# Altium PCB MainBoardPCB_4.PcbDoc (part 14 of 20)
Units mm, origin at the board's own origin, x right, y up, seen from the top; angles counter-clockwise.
Board outline 333.63 x 349.38 mm, 16 copper layers (L1, L2 (GND), L3 (Sign), L4 (GND), L5 (Sign), L6 (PWR/GND), L7(PWR/GND), L8 (Plane_GND), L9 (PWR/GND), L10 (PWR/GND), L11 (PWR/GND), L12 (Sign), L13 (GND), L14 (Sign), L15 (GND), L16), stack 2.502 mm thick; 2205 components, 1648 nets, 8314 pads, 3172 vias.
Unrouted connection lines stored in the file: 5141.
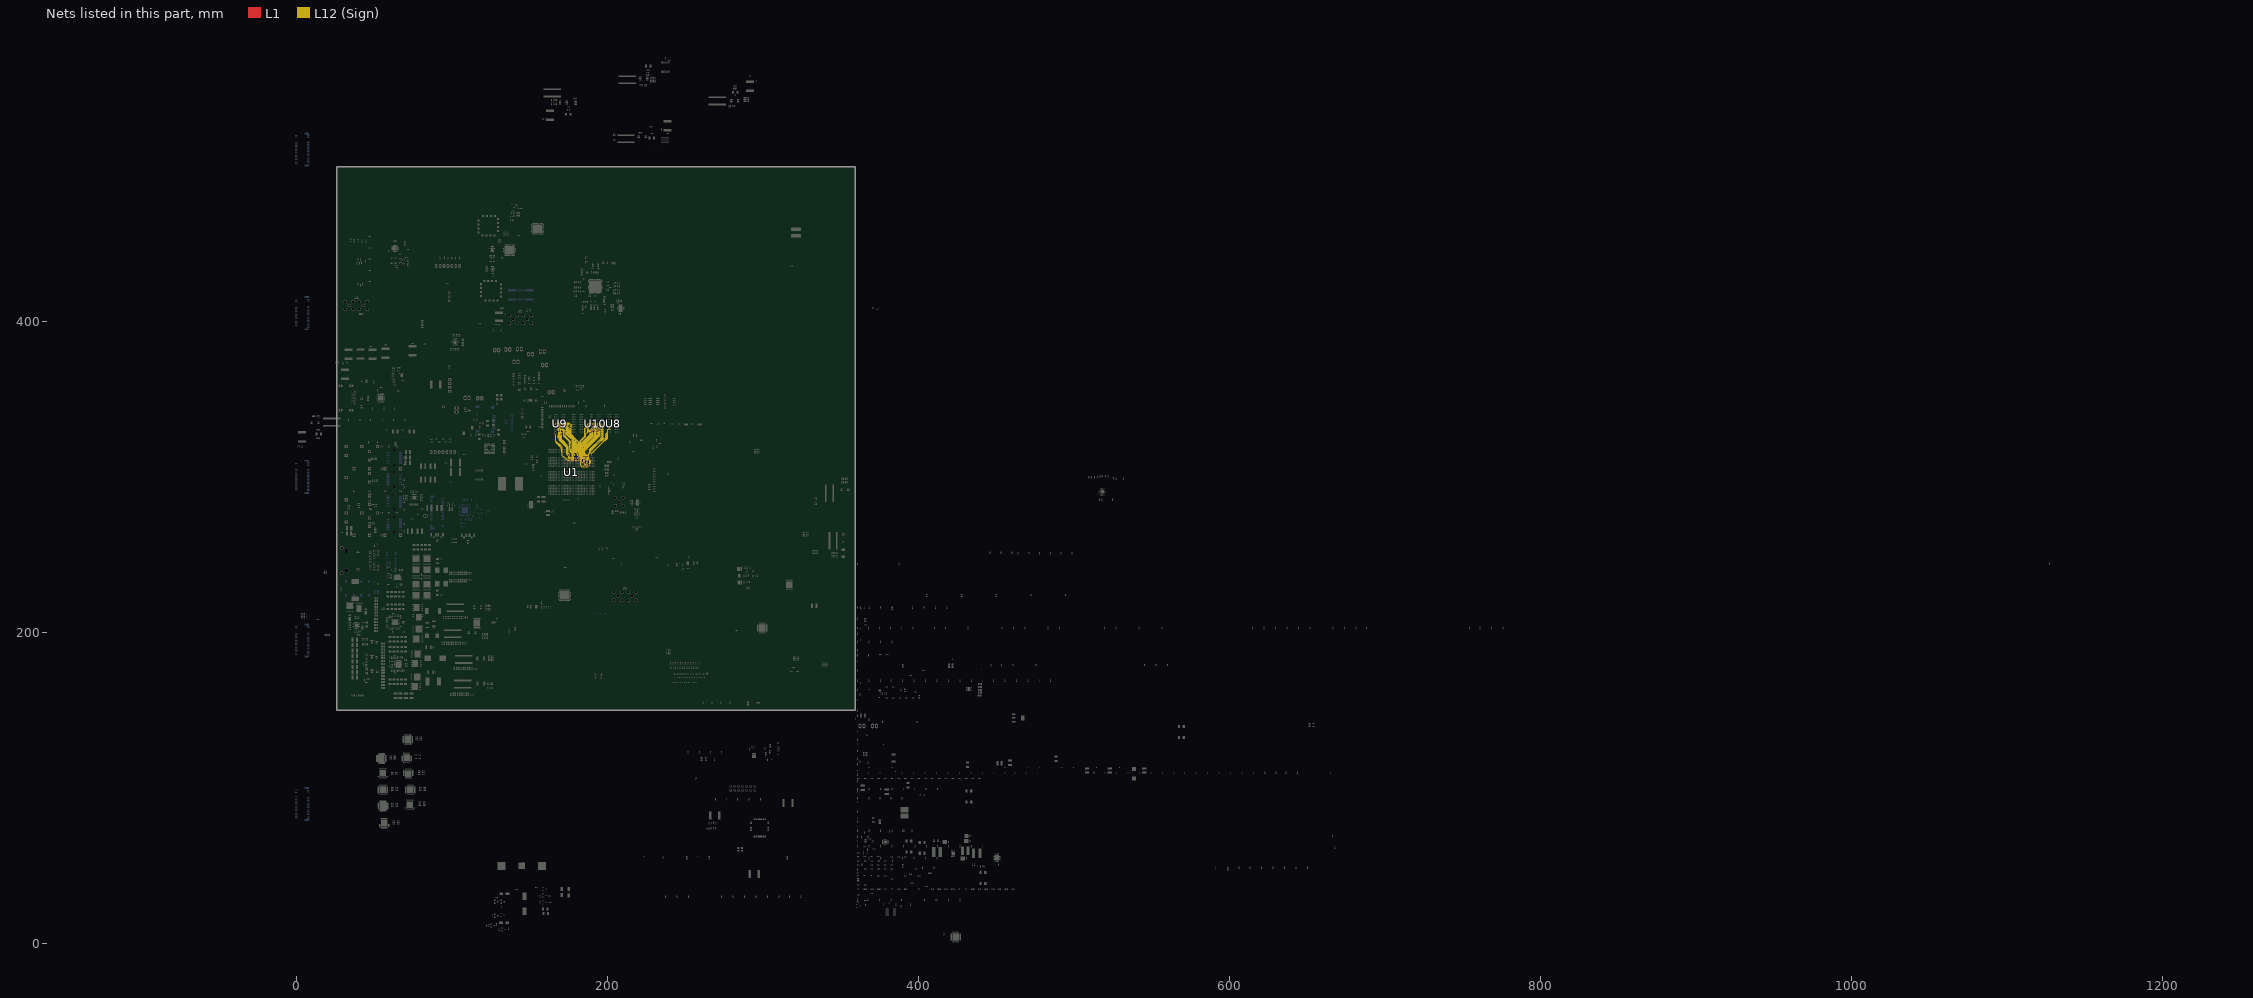
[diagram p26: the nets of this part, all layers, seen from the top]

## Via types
v1: diameter 0.5, hole 0.2, L1 to L16, tented both sides, 1153 vias
v2: diameter 0.5/0.35/0.35/0.35/0.35/0.35/0.35/0.35/0.35/0.35/0.35/0.35/0.35/0.35/0.35/0.5 (per signal layer), hole 0.2, L1 to L16, tented both sides, 548 vias
v3: diameter 0.5, hole 0.2, L1 to L16, 522 vias
v4: diameter 0.5/0.35/0.35/0.35/0.35/0.35/0.35/0.35/0.35/0.35/0.35/0.35/0.35/0.35/0.35/0.5 (per signal layer), hole 0.15, L1 to L16, tented both sides, 266 vias
v5: diameter 0.8, hole 0.4, L1 to L16, tented both sides, 164 vias
v6: diameter 0.35/0/0.35 (per signal layer), hole 0.127, L1 to L3 (Sign), tented both sides, 132 vias
v7: diameter 2.54, hole 1.02, L1 to L16, 125 vias
v8: diameter 1.4, hole 0.5, L1 to L16, tented both sides, 80 vias
v9: diameter 0.35, hole 0.127, L1 to L2 (GND), tented both sides, 36 vias
v10: diameter 0.4, hole 0.2, L1 to L16, 16 vias
v11: diameter 0.25, hole 0.2, L1 to L16, 16 vias
v12: diameter 5, hole 3, L1 to L16, 15 vias
v13: diameter 0.3, hole 0.2, L1 to L16, 15 vias
v14: diameter 0.45, hole 0.15, L1 to L16, 12 vias
v15: diameter 0.5/0.35/0.35/0.35/0.35/0.35/0.35/0.35/0.35/0.35/0.35/0.35/0.35/0.35/0.35/0.45 (per signal layer), hole 0.15, L1 to L16, tented both sides, 10 vias
v16: diameter 0.2/0/0.2 (per signal layer), hole 0.1, L1 to L3 (Sign), tented both sides, 9 vias
v17: diameter 0.4, hole 0.1, L1 to L16, 7 vias
v18: diameter 0.5, hole 0.2, L3 (Sign) to L6 (PWR/GND), tented both sides, 6 vias
v19: diameter 1.65, hole 1.65, L1 to L16, 6 vias
v20: diameter 1.15, hole 1.15, L1 to L16, 6 vias
v21: diameter 0.35/0/0.35 (per signal layer), hole 0.127, L14 (Sign) to L16, tented both sides, 5 vias
v22: diameter 0.2, hole 0.1, L1 to L16, 4 vias
v23: diameter 0.4, hole 0.2, L1 to L16, tented both sides, 2 vias
v24: diameter 0.4, hole 0.15, L1 to L16, 2 vias
v25: diameter 0.508, hole 0.127, L1 to L2 (GND), 2 vias
v26: diameter 0.508, hole 0.127, L2 (GND) to L3 (Sign), 2 vias
v27: diameter 0.5/0.35/0.35/0.35/0.35/0.35/0.35/0.35/0.35/0.35/0.35/0.35/0.35/0.35/0.35/0.5 (per signal layer), hole 0.15, L1 to L16, 2 vias
v28: diameter 0.35, hole 0.127, L3 (Sign) to L6 (PWR/GND), tented both sides, 2 vias
v29: diameter 5.5, hole 3.5, L1 to L16, 1 vias
v30: diameter 0.5/0.35/0.35/0.35/0.35/0.35/0.35/0.35/0.35/0.35/0.35/0.35/0.35/0.35/0.35/0.5 (per signal layer), hole 0.2, L1 to L16, 1 vias
v31: diameter 0.35/0.35/0.35 (per signal layer), hole 0.127, L1 to L3 (Sign), tented both sides, 1 vias
v32: diameter 0.45/0/0.45 (per signal layer), hole 0.15, L1 to L3 (Sign), tented both sides, 1 vias
v33: diameter 0.45/0/0.45 (per signal layer), hole 0.2, L14 (Sign) to L16, tented both sides, 1 vias
v34: diameter 0.35, hole 0.127, L2 (GND) to L3 (Sign), 1 vias
v35: diameter 0.35, hole 0.127, L1 to L2 (GND), 1 vias

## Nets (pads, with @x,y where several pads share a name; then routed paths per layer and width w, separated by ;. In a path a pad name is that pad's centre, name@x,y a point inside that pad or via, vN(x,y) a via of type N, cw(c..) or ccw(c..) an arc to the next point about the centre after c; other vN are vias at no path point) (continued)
DDR4_DQ15: U1.AH26 U8.D4 | length 32
  L1 w0.116: U1.AH26@189.397,313.539 v2(189.884,314.027) ; v4(201.653,330.864) U8.D4@202.057,330.46
  L12 (Sign) w0.092: v2(189.884,314.027) 189.884,315.174 197.57,322.859 197.878,323.167 ccw(c197.8,323.245) 197.878,323.322 197.67,323.53 cw(c197.748,323.607) 197.67,323.685 197.903,323.918 cw(c197.981,323.841) 198.059,323.918 198.344,323.633 198.629,323.348 ccw(c198.707,323.426) 198.784,323.348 199.017,323.581 ccw(c198.94,323.659) 199.017,323.737 198.732,324.022 198.447,324.307 cw(c198.525,324.384) 198.447,324.462 198.68,324.695 cw(c198.758,324.618) 198.836,324.695 199.121,324.41 199.406,324.125 ccw(c199.484,324.203) 199.561,324.125 199.794,324.358 ccw(c199.717,324.436) 199.794,324.513 199.587,324.721 cw(c199.665,324.799) 199.587,324.876 199.704,324.993 199.704,325.166 cw(c199.736,325.166) 199.736,325.199 200.106,325.199 ccw(c200.106,325.309) 200.216,325.309 200.216,325.638 ccw(c200.106,325.638) 200.106,325.748 199.704,325.748 199.22,325.748 cw(c199.22,325.858) 199.11,325.858 199.11,326.188 cw(c199.22,326.188) 199.22,326.298 199.704,326.298 200.106,326.298 ccw(c200.106,326.408) 200.216,326.408 200.216,326.737 ccw(c200.106,326.737) 200.106,326.847 199.704,326.847 199.22,326.847 cw(c199.22,326.957) 199.11,326.957 199.11,327.287 cw(c199.22,327.287) 199.22,327.397 199.704,327.397 200.106,327.397 ccw(c200.106,327.506) 200.216,327.506 200.216,327.836 ccw(c200.106,327.836) 200.106,327.946 199.813,327.946 cw(c199.813,328.056) 199.704,328.056 199.704,328.221 200.207,328.724 200.207,330.233 200.838,330.864 v4(201.653,330.864)
DDR4_DQ16: U1.AD22 U10.G2 | length 41.3
  L1 w0.116: v2(184.909,309.052) U1.AD22@185.397,309.539 ; v4(194.193,332.457) U10.G2@194.597,332.86
  L12 (Sign) w0.092: v2(184.909,309.052) 184.617,309.344 183.735,309.344 183.013,310.066 183.013,322.87 186.169,326.026 186.169,327.624 186.993,328.447 187.173,328.447 ccw(c187.173,328.743) 187.469,328.743 187.469,329.334 cw(c187.618,329.334) 187.618,329.484 187.621,329.484 ccw(c187.621,329.633) 187.77,329.633 187.77,329.833 ccw(c187.621,329.833) 187.621,329.982 187.469,329.982 187.317,329.982 cw(c187.317,330.132) 187.167,330.132 187.167,330.331 cw(c187.317,330.331) 187.317,330.481 187.469,330.481 187.621,330.481 ccw(c187.621,330.63) 187.77,330.63 187.77,330.83 ccw(c187.621,330.83) 187.621,330.979 187.618,330.979 cw(c187.618,331.129) 187.469,331.129 187.469,331.229 cw(c187.621,331.229) 187.621,331.381 187.897,331.381 cw(c187.897,331.179) 188.098,331.179 188.098,330.098 ccw(c188.48,330.098) 188.48,329.717 188.789,329.717 190.597,331.525 190.597,331.767 190.966,332.136 191.186,332.136 191.27,332.136 191.69,332.136 ccw(c191.69,332.316) 191.87,332.316 191.87,333.26 cw(c192.05,333.26) 192.05,333.44 192.29,333.44 cw(c192.29,333.26) 192.47,333.26 192.47,332.136 192.47,331.511 ccw(c192.65,331.511) 192.65,331.331 192.89,331.331 ccw(c192.89,331.511) 193.07,331.511 193.07,331.956 cw(c193.25,331.956) 193.25,332.136 193.37,332.136 193.872,332.136 v4(194.193,332.457)
DDR4_DQ17: U1.AE22 U10.F4 | length 40.2
  L1 w0.116: v2(185.909,309.052) U1.AE22@186.397,309.539 ; U10.F4@190.597,332.06 v4(191,331.657)
  L12 (Sign) w0.092: v2(185.909,309.052) 186.095,309.238 184.856,310.477 183.789,310.477 183.397,310.869 183.397,321.424 189.714,327.741 189.714,328.59 189.714,328.879 ccw(c189.64,328.879) 189.64,328.953 188.047,328.953 cw(c188.047,329.103) 187.897,329.103 187.897,329.302 cw(c188.047,329.302) 188.047,329.452 189.564,329.452 ccw(c189.564,329.601) 189.714,329.601 189.714,329.701 189.714,330.125 190.805,331.216 191.249,331.216 192.024,330.441 194.404,330.441 ccw(c194.404,330.581) 194.543,330.581 194.543,330.955 ccw(c194.409,330.955) 194.409,331.089 192.497,331.089 cw(c192.497,331.457) 192.129,331.457 ccw(c191.929,331.457) 191.929,331.657 v4(191,331.657)
DDR4_DQ18: U1.AF22 U10.H3 | length 39.4
  L1 w0.116: U1.AF22@187.397,309.539 v2(187.884,309.052) ; U10.H3@193.797,333.66 v4(194.2,333.257)
  L12 (Sign) w0.092: v2(187.884,309.052) 187.906,309.052 188.428,309.573 188.428,309.987 188.042,310.373 188.013,310.373 187.165,311.221 187.165,312.828 187.23,312.894 187.23,313.51 185.622,315.118 185.622,316.741 194.831,325.95 194.831,326.1 cw(c194.981,326.1) 194.981,326.25 195.031,326.25 ccw(c195.031,326.4) 195.181,326.4 195.181,326.7 ccw(c195.031,326.7) 195.031,326.85 194.831,326.85 194.605,326.85 cw(c194.605,327) 194.455,327 194.455,327.3 cw(c194.605,327.3) 194.605,327.45 194.831,327.45 195.031,327.45 ccw(c195.031,327.601) 195.181,327.601 195.181,327.901 ccw(c195.031,327.901) 195.031,328.051 194.831,328.051 194.605,328.051 cw(c194.605,328.201) 194.455,328.201 194.455,328.501 cw(c194.605,328.501) 194.605,328.651 194.831,328.651 195.031,328.651 ccw(c195.031,328.801) 195.181,328.801 195.181,329.101 ccw(c195.031,329.101) 195.031,329.251 194.831,329.251 194.51,329.251 cw(c194.51,329.401) 194.36,329.401 194.36,329.701 cw(c194.51,329.701) 194.51,329.851 194.685,329.851 ccw(c194.685,329.997) 194.831,329.997 194.831,331.219 194.591,331.459 194.591,331.753 195.229,332.39 195.598,332.39 ccw(c195.598,332.524) 195.732,332.524 195.732,332.699 ccw(c195.616,332.699) 195.616,332.816 192.918,332.816 cw(c192.918,332.947) 192.788,332.947 192.788,333.081 cw(c192.955,333.081) 192.955,333.248 194.2,333.248 v4(194.2,333.257)
DDR4_DQ19: U1.AG21 U10.H4 | length 38.3
  L1 w0.116: v2(187.909,308.052) U1.AG21@188.397,308.539 ; v4(190.193,333.257) U10.H4@190.597,333.66
  L12 (Sign) w0.092: v2(187.909,308.052) 188.038,308.181 188.038,308.211 188.094,308.266 188.094,308.513 188.812,309.231 188.812,310.147 188.201,310.757 188.172,310.757 187.549,311.38 187.549,312.669 187.614,312.735 187.614,314.572 188.785,315.743 188.785,317.598 196.098,324.911 196.098,333.027 195.793,333.332 195.535,333.332 195.206,333.66 193.332,333.66 192.102,333.66 cw(c192.102,333.81) 191.952,333.81 191.952,334.282 ccw(c191.802,334.282) 191.802,334.432 191.502,334.432 ccw(c191.502,334.282) 191.352,334.282 191.352,333.81 cw(c191.202,333.81) 191.202,333.66 191.052,333.66 190.649,333.257 v4(190.193,333.257)
DDR4_DQ20: U1.AD20 U10.H2 | length 41.2
  L1 w0.116: v1(184.909,307.052) U1.AD20@185.397,307.539 ; v4(194.193,334.064) U10.H2@194.597,333.66
  L12 (Sign) w0.092: v1(184.909,307.052) 185.513,307.656 188.098,307.656 188.254,307.812 188.254,308.155 188.256,308.155 188.286,308.185 188.286,308.434 189.004,309.151 189.004,310.226 188.281,310.949 188.251,310.949 187.741,311.459 187.741,312.59 187.806,312.655 187.806,314.492 189.04,315.725 189.04,317.58 197.208,325.749 197.208,325.831 197.208,326.337 ccw(c197.058,326.337) 197.058,326.487 196.817,326.487 cw(c196.817,326.637) 196.667,326.637 196.667,326.937 cw(c196.817,326.937) 196.817,327.087 197.058,327.087 ccw(c197.058,327.237) 197.208,327.237 197.208,327.537 ccw(c197.058,327.537) 197.058,327.687 196.817,327.687 cw(c196.817,327.837) 196.667,327.837 196.667,328.137 cw(c196.817,328.137) 196.817,328.287 197.058,328.287 ccw(c197.058,328.437) 197.208,328.437 197.208,328.737 ccw(c197.058,328.737) 197.058,328.887 196.817,328.887 cw(c196.817,329.038) 196.667,329.038 196.667,329.338 cw(c196.817,329.338) 196.817,329.488 197.058,329.488 ccw(c197.058,329.638) 197.208,329.638 197.208,329.938 ccw(c197.058,329.938) 197.058,330.088 196.817,330.088 cw(c196.817,330.238) 196.667,330.238 196.667,330.538 cw(c196.817,330.538) 196.817,330.688 197.058,330.688 ccw(c197.058,330.838) 197.208,330.838 197.208,331.288 197.208,331.888 197.208,332.189 195.873,333.524 195.629,333.524 195.3,333.852 194.746,333.852 194.534,334.064 v4(194.193,334.064)
DDR4_DQ21: U1.AF20 U10.H5 | length 39.1
  L1 w0.116: v2(186.909,307.052) U1.AF20@187.397,307.539 ; v4(189.393,333.257) U10.H5@189.797,333.66
  L12 (Sign) w0.092: v2(186.909,307.052) 186.656,306.799 186.385,306.799 186.24,306.654 183.747,306.654 182.982,307.42 182.982,309.705 182.821,309.866 182.821,323.125 185.852,326.156 185.852,331.058 185.958,331.164 ccw(c185.852,331.27) 185.958,331.376 185.83,331.504 cw(c185.936,331.61) 185.83,331.716 186.042,331.928 cw(c186.148,331.822) 186.254,331.928 186.488,331.694 186.762,331.421 ccw(c186.868,331.527) 186.974,331.421 187.186,331.633 ccw(c187.08,331.739) 187.186,331.845 186.913,332.119 186.639,332.392 cw(c186.746,332.498) 186.639,332.604 186.852,332.816 cw(c186.958,332.71) 187.064,332.816 187.337,332.543 187.611,332.27 ccw(c187.717,332.376) 187.823,332.27 188.035,332.482 ccw(c187.929,332.588) 188.035,332.694 187.868,332.861 cw(c187.974,332.967) 187.868,333.073 188.058,333.264 188.455,333.66 189.195,333.66 189.393,333.462 v4(189.393,333.257)
DDR4_DQ22: U1.AE20 U10.J3 | length 41
  L1 w0.116: v2(185.909,307.052) U1.AE20@186.397,307.539 ; v4(193.393,334.057) U10.J3@193.797,334.46
  L12 (Sign) w0.092: v2(185.909,307.052) 186.261,307.404 188.117,307.404 188.478,307.765 188.478,308.354 189.196,309.072 189.196,310.306 188.361,311.141 188.331,311.141 187.933,311.539 187.933,312.51 187.998,312.576 187.998,314.412 189.397,315.811 189.397,316.791 193.735,321.129 195.406,322.799 ccw(c195.299,322.905) 195.406,323.011 195.343,323.074 cw(c195.449,323.18) 195.343,323.286 195.555,323.498 cw(c195.661,323.392) 195.767,323.498 195.936,323.33 196.105,323.161 ccw(c196.211,323.267) 196.317,323.161 196.529,323.373 ccw(c196.423,323.479) 196.529,323.586 196.36,323.754 196.192,323.923 cw(c196.298,324.029) 196.192,324.135 196.404,324.347 cw(c196.51,324.241) 196.616,324.347 196.785,324.179 196.954,324.01 ccw(c197.06,324.116) 197.166,324.01 197.378,324.222 ccw(c197.272,324.328) 197.378,324.434 197.315,324.497 cw(c197.422,324.603) 197.315,324.709 197.421,324.815 197.421,332.246 195.952,333.716 195.708,333.716 195.375,334.049 195.122,334.049 194.711,334.46 193.797,334.46 v4(193.393,334.057)
DDR4_DQ23: U1.AG20 U10.J4 | length 38.7
  L1 w0.116: v2(187.909,307.052) U1.AG20@188.397,307.539 ; v4(190.193,334.057) U10.J4@190.597,334.46
  L12 (Sign) w0.092: v2(187.909,307.052) 187.308,306.451 183.642,306.451 183.23,306.863 183.23,306.899 182.79,307.34 182.79,309.626 182.629,309.786 182.629,323.307 185.59,326.267 185.59,331.501 185.587,331.503 185.587,331.717 185.59,331.72 185.59,331.906 188.144,334.46 189.789,334.46 v4(190.193,334.057)
DDR4_DQ24: U1.AG23 U10.A3 | length 27.3
  L1 w0.116: v2(187.909,310.052) U1.AG23@188.397,310.539 ; v4(193.393,327.657) U10.A3@193.797,328.06
  L12 (Sign) w0.092: v2(187.909,310.052) 187.431,310.052 186.578,310.905 186.578,313.348 185.046,314.88 185.046,317.652 191.062,323.669 191.295,323.902 cw(c191.368,323.829) 191.44,323.902 ccw(c191.58,324.043) 191.721,323.902 191.792,323.973 ccw(c191.651,324.114) 191.792,324.255 191.72,324.326 cw(c191.817,324.423) 191.72,324.519 191.88,324.679 cw(c191.976,324.583) 192.073,324.679 192.145,324.607 ccw(c192.286,324.748) 192.427,324.607 192.497,324.678 ccw(c192.356,324.819) 192.497,324.96 192.425,325.032 cw(c192.522,325.128) 192.425,325.224 192.585,325.384 cw(c192.681,325.288) 192.778,325.384 192.85,325.312 ccw(c192.991,325.453) 193.132,325.312 193.203,325.382 ccw(c193.062,325.523) 193.203,325.664 cw(c193.275,325.737) 193.203,325.809 193.307,325.913 193.393,325.999 193.393,326.263 193.393,326.311 ccw(c193.293,326.311) 193.293,326.41 193.012,326.41 cw(c193.012,326.51) 192.912,326.51 192.912,326.809 cw(c193.012,326.809) 193.012,326.909 193.393,326.909 193.955,326.909 ccw(c193.955,327.009) 194.055,327.009 194.055,327.308 ccw(c193.955,327.308) 193.955,327.408 193.493,327.408 cw(c193.493,327.507) 193.393,327.507 v4(193.393,327.657)
DDR4_DQ25: U1.AF23 U10.B5 | length 28.1
  L1 w0.116: v2(186.909,310.052) U1.AF23@187.397,310.539 ; v4(189.393,328.457) U10.B5@189.797,328.86
  L12 (Sign) w0.092: v2(186.909,310.052) 186.909,309.481 186.588,309.16 186.588,308.731 186.233,308.375 185.675,308.375 185.242,308.808 185.242,309.33 185.033,309.539 183.837,309.539 183.205,310.171 183.205,321.724 188.981,327.5 188.981,328.045 v4(189.393,328.457)
DDR4_DQ26: U1.AF25 U10.C3 | length 27.7
  L1 w0.116: v2(186.909,313.027) U1.AF25@187.397,312.539 ; v4(193.393,329.257) U10.C3@193.797,329.66
  L12 (Sign) w0.092: v2(186.909,313.027) 186.909,313.287 185.238,314.959 185.238,317.146 188.243,320.151 188.606,320.514 ccw(c188.534,320.587) 188.606,320.659 188.609,320.656 ; 188.61,320.655 cw(c188.751,320.796) 188.61,320.937 188.68,321.008 cw(c188.821,320.867) 188.962,321.008 189.031,320.939 189.145,320.825 ccw(c189.286,320.966) 189.427,320.825 189.497,320.895 ccw(c189.356,321.036) 189.497,321.177 189.383,321.292 189.315,321.36 cw(c189.456,321.501) 189.315,321.642 189.385,321.713 cw(c189.526,321.572) 189.667,321.713 189.736,321.644 189.85,321.53 ccw(c189.991,321.671) 190.132,321.53 190.203,321.6 ccw(c190.062,321.742) 190.203,321.883 190.088,321.997 190.02,322.065 cw(c190.161,322.206) 190.02,322.347 190.09,322.418 cw(c190.231,322.277) 190.372,322.418 190.441,322.349 190.555,322.235 ccw(c190.696,322.376) 190.837,322.235 190.908,322.306 ccw(c190.767,322.447) 190.908,322.588 190.794,322.702 190.725,322.771 cw(c190.866,322.912) 190.725,323.053 190.795,323.123 cw(c190.936,322.982) 191.077,323.123 191.146,323.054 191.264,322.937 ccw(c191.405,323.078) 191.546,322.937 191.616,323.007 ccw(c191.475,323.148) 191.616,323.289 cw(c191.734,323.407) 191.616,323.525 191.675,323.583 194.246,326.155 194.246,327.8 194.246,327.949 ccw(c194.147,327.949) 194.147,328.049 193.612,328.049 cw(c193.612,328.149) 193.512,328.149 193.512,328.448 cw(c193.612,328.448) 193.612,328.548 194.147,328.548 ccw(c194.147,328.647) 194.246,328.647 194.246,328.879 193.84,329.286 193.422,329.286 v4(193.393,329.257)
DDR4_DQ27: U1.AE23 U10.C4 | length 29.6
  L1 w0.116: v2(185.909,310.052) U1.AE23@186.397,310.539 ; U10.C4@190.597,329.66 v4(191,329.257)
  L12 (Sign) w0.092: v2(185.909,310.052) 185.331,310.63 185.331,312.165 185.073,312.423 184.788,312.423 184.204,313.006 184.204,319.358 184.239,319.392 184.309,319.463 ccw(c184.204,319.569) 184.309,319.674 184.158,319.826 cw(c184.264,319.931) 184.158,320.037 184.299,320.178 cw(c184.405,320.072) 184.511,320.178 184.768,319.921 184.857,319.832 ccw(c184.963,319.938) 185.069,319.832 185.21,319.973 ccw(c185.104,320.079) 185.21,320.184 185.12,320.274 184.838,320.556 cw(c184.943,320.662) 184.838,320.768 184.979,320.909 cw(c185.084,320.803) 185.19,320.909 185.473,320.626 185.562,320.537 ccw(c185.668,320.643) 185.774,320.537 185.915,320.678 ccw(c185.809,320.784) 185.915,320.89 185.825,320.979 185.543,321.262 cw(c185.649,321.367) 185.543,321.473 185.684,321.614 cw(c185.79,321.508) 185.895,321.614 186.072,321.437 ccw(c186.178,321.543) 186.284,321.437 186.938,322.091 190.525,325.679 190.592,325.746 ccw(c190.487,325.851) 190.592,325.957 190.405,326.145 cw(c190.511,326.251) 190.405,326.356 190.546,326.497 cw(c190.652,326.392) 190.757,326.497 191.051,326.204 191.183,326.072 ccw(c191.289,326.177) 191.395,326.072 191.536,326.213 ccw(c191.43,326.318) 191.536,326.424 191.509,326.451 cw(c191.615,326.557) 191.509,326.662 191.579,326.733 191.579,328.677 v4(191,329.257)
DDR4_DQ28: U1.AC22 U10.C2 | length 31.5
  L1 w0.116: v1(183.909,310.027) U1.AC22@184.397,309.539 ; v4(194.193,330.064) U10.C2@194.597,329.66
  L12 (Sign) w0.092: v1(183.909,310.027) 184.909,310.027 185.481,309.455 185.481,308.84 185.754,308.567 186.127,308.567 186.386,308.826 186.386,310.236 186.386,310.578 ccw(c186.286,310.578) 186.286,310.678 186.128,310.678 cw(c186.128,310.778) 186.028,310.778 186.028,311.077 cw(c186.128,311.077) 186.128,311.177 186.286,311.177 ccw(c186.286,311.277) 186.386,311.277 186.386,311.675 186.386,311.925 186.386,313.268 184.854,314.8 184.854,317.924 192.72,325.791 192.72,329.25 193.16,329.69 193.819,329.69 v4(194.193,330.064)
DDR4_DQ29: U1.AC23 U10.C5 | length 31.3
  L1 w0.116: v1(183.909,311.027) U1.AC23@184.397,310.539 ; U10.C5@189.797,329.66 v4(190.2,329.257)
  L12 (Sign) w0.092: v1(183.909,311.027) 184.266,311.383 184.266,312.156 183.72,312.702 183.72,320.943 183.79,321.014 ccw(c183.684,321.119) 183.79,321.225 183.746,321.269 cw(c183.852,321.375) 183.746,321.481 183.887,321.622 cw(c183.993,321.516) 184.099,321.622 184.249,321.472 184.398,321.322 ccw(c184.504,321.428) 184.61,321.322 184.751,321.463 ccw(c184.645,321.569) 184.751,321.675 184.601,321.825 184.451,321.974 cw(c184.557,322.08) 184.451,322.186 184.592,322.327 cw(c184.698,322.221) 184.804,322.327 184.954,322.177 185.103,322.028 ccw(c185.209,322.133) 185.315,322.028 185.456,322.169 ccw(c185.35,322.274) 185.456,322.38 185.306,322.53 185.157,322.679 cw(c185.262,322.785) 185.157,322.891 185.298,323.032 cw(c185.403,322.926) 185.509,323.032 185.659,322.882 185.808,322.733 ccw(c185.914,322.838) 186.02,322.733 186.161,322.874 ccw(c186.055,322.979) 186.161,323.085 186.011,323.235 185.862,323.385 cw(c185.967,323.49) 185.862,323.596 186.003,323.737 cw(c186.108,323.631) 186.214,323.737 186.364,323.587 186.514,323.438 ccw(c186.619,323.544) 186.725,323.438 186.866,323.579 ccw(c186.76,323.685) 186.866,323.79 186.716,323.94 186.567,324.09 cw(c186.673,324.195) 186.567,324.301 186.708,324.442 cw(c186.814,324.336) 186.919,324.442 187.069,324.293 187.219,324.143 ccw(c187.324,324.249) 187.43,324.143 187.571,324.284 ccw(c187.465,324.39) 187.571,324.495 187.422,324.645 187.272,324.795 cw(c187.378,324.901) 187.272,325.006 187.413,325.147 cw(c187.519,325.042) 187.625,325.147 187.774,324.998 187.924,324.848 ccw(c188.03,324.954) 188.135,324.848 188.276,324.989 ccw(c188.171,325.095) 188.276,325.201 188.127,325.35 187.977,325.5 cw(c188.083,325.606) 187.977,325.711 188.118,325.852 cw(c188.224,325.747) 188.33,325.852 188.479,325.703 188.629,325.553 ccw(c188.735,325.659) 188.84,325.553 188.982,325.694 ccw(c188.876,325.8) 188.982,325.906 188.832,326.055 188.682,326.205 cw(c188.788,326.311) 188.682,326.417 188.823,326.558 cw(c188.929,326.452) 189.035,326.558 189.079,326.514 ccw(c189.184,326.619) 189.29,326.514 190.2,327.424 190.2,327.469 v4(190.2,329.257)
DDR4_DQ30: U1.AD25 U10.D3 | length 29.3
  L1 w0.116: v2(184.909,313.027) U1.AD25@185.397,312.539 ; v4(193.393,330.057) U10.D3@193.797,330.46
  L12 (Sign) w0.092: v2(184.909,313.027) 184.998,313.027 ccw(c184.998,313.195) 185.166,313.195 185.166,313.521 cw(c185.255,313.521) 185.255,313.61 ccw(c185.255,313.711) 185.356,313.711 185.356,313.826 ccw(c185.272,313.826) 185.272,313.911 184.831,313.911 cw(c184.831,314.084) 184.658,314.084 184.658,318.524 184.683,318.549 184.725,318.591 cw(c184.795,318.52) 184.866,318.591 184.976,318.48 ccw(c185.047,318.551) 185.117,318.48 185.329,318.692 ccw(c185.258,318.762) 185.329,318.833 185.148,319.014 185.052,319.11 cw(c185.122,319.18) 185.052,319.251 185.263,319.462 cw(c185.334,319.392) 185.404,319.462 185.5,319.366 185.681,319.185 ccw(c185.752,319.256) 185.822,319.185 186.034,319.397 ccw(c185.963,319.467) 186.034,319.538 185.853,319.719 185.757,319.815 cw(c185.827,319.885) 185.757,319.956 185.968,320.167 cw(c186.039,320.097) 186.109,320.167 186.205,320.071 186.386,319.89 ccw(c186.457,319.961) 186.527,319.89 186.739,320.102 ccw(c186.668,320.172) 186.739,320.243 186.558,320.424 186.462,320.52 cw(c186.532,320.59) 186.462,320.661 186.673,320.873 cw(c186.744,320.802) 186.814,320.873 186.91,320.776 187.091,320.596 ccw(c187.162,320.666) 187.232,320.596 187.444,320.807 ccw(c187.373,320.878) 187.444,320.948 187.334,321.059 cw(c187.404,321.129) 187.334,321.2 187.439,321.305 191.955,325.821 192.174,325.821 192.176,325.823 192.176,326.107 cw(c192.276,326.107) 192.276,326.206 192.279,326.206 ccw(c192.279,326.306) 192.379,326.306 192.379,326.605 ccw(c192.279,326.605) 192.279,326.705 192.176,326.705 192.072,326.705 cw(c192.072,326.805) 191.973,326.805 191.973,327.104 cw(c192.072,327.104) 192.072,327.204 192.176,327.204 192.279,327.204 ccw(c192.279,327.303) 192.379,327.303 192.379,327.602 ccw(c192.279,327.602) 192.279,327.702 192.176,327.702 192.072,327.702 cw(c192.072,327.802) 191.973,327.802 191.973,328.101 cw(c192.072,328.101) 192.072,328.201 192.176,328.201 192.279,328.201 ccw(c192.279,328.3) 192.379,328.3 192.379,328.6 ccw(c192.279,328.6) 192.279,328.699 192.176,328.699 192.072,328.699 cw(c192.072,328.799) 191.973,328.799 191.973,329.098 cw(c192.072,329.098) 192.072,329.198 192.176,329.198 192.279,329.198 ccw(c192.279,329.298) 192.379,329.298 192.379,329.597 ccw(c192.279,329.597) 192.279,329.697 192.276,329.697 cw(c192.276,329.796) 192.176,329.796 192.176,329.946 192.287,330.057 v4(193.393,330.057)
DDR4_DQ31: U1.AC24 U10.D4 | length 30.7
  L1 w0.116: U1.AC24@184.397,311.539 v1(184.884,311.052) ; v4(190.193,330.057) U10.D4@190.597,330.46
  L12 (Sign) w0.092: v1(184.884,311.052) 184.884,311.372 184.519,311.737 184.519,312.175 183.912,312.782 183.912,320.157 184.849,321.094 185.762,322.008 ccw(c185.712,322.059) 185.762,322.11 185.763,322.109 cw(c185.869,322.214) 185.763,322.32 185.905,322.461 cw(c186.01,322.355) 186.116,322.461 186.166,322.411 186.279,322.299 ccw(c186.384,322.405) 186.49,322.299 186.631,322.44 ccw(c186.525,322.546) 186.631,322.651 186.518,322.764 186.469,322.814 cw(c186.574,322.92) 186.469,323.025 186.61,323.166 cw(c186.715,323.061) 186.821,323.166 186.871,323.117 186.984,323.004 ccw(c187.089,323.11) 187.195,323.004 187.336,323.145 ccw(c187.23,323.251) 187.336,323.356 187.224,323.469 187.174,323.519 cw(c187.28,323.625) 187.174,323.73 187.315,323.872 cw(c187.421,323.766) 187.526,323.872 187.576,323.822 187.689,323.709 ccw(c187.795,323.815) 187.9,323.709 188.041,323.85 ccw(c187.936,323.956) 188.041,324.062 187.929,324.174 187.879,324.224 cw(c187.985,324.33) 187.879,324.436 188.02,324.577 cw(c188.126,324.471) 188.231,324.577 188.281,324.527 188.394,324.414 ccw(c188.5,324.52) 188.605,324.414 188.746,324.555 ccw(c188.641,324.661) 188.746,324.767 188.634,324.879 188.584,324.929 cw(c188.69,325.035) 188.584,325.141 188.725,325.282 cw(c188.831,325.176) 188.937,325.282 188.986,325.232 189.099,325.119 ccw(c189.205,325.225) 189.311,325.119 189.452,325.26 ccw(c189.346,325.366) 189.452,325.472 189.339,325.585 189.261,325.662 cw(c189.367,325.768) 189.261,325.874 189.402,326.015 cw(c189.508,325.909) 189.614,326.015 189.691,325.937 189.804,325.824 ccw(c189.91,325.93) 190.016,325.824 190.157,325.965 ccw(c190.051,326.071) 190.157,326.177 190.044,326.29 189.931,326.402 cw(c190.037,326.508) 189.931,326.614 190.072,326.755 cw(c190.178,326.649) 190.284,326.755 190.291,326.748 ccw(c190.397,326.854) 190.502,326.748 190.573,326.818 190.573,329.438 cw(c190.751,329.438) 190.751,329.616 191.3,329.616 ccw(c191.3,329.73) 191.414,329.73 191.414,329.933 ccw(c191.173,329.933) 191.173,330.175 190.311,330.175 ccw(c190.311,330.057) v4(190.193,330.057)
DDR4_DQ32: U1.U24 U9.G2 | length 41.6
  L1 w0.116: v4(171.272,332.457) U9.G2@171.676,332.86 ; U1.U24@178.397,311.539 v1(178.884,312.027)
  L12 (Sign) w0.092: v4(171.272,332.457) 171.704,332.025 171.704,330.594 172.668,329.63 173.152,329.63 173.169,329.63 ccw(c173.169,329.73) 173.268,329.73 173.268,329.987 cw(c173.368,329.987) 173.368,330.087 173.667,330.087 cw(c173.667,329.987) 173.767,329.987 173.767,329.63 173.767,329.273 ccw(c173.867,329.273) 173.867,329.173 174.166,329.173 ccw(c174.166,329.273) 174.266,329.273 174.266,329.53 cw(c174.365,329.53) 174.365,329.63 174.515,329.63 174.69,329.455 174.69,329.305 ccw(c174.79,329.305) 174.79,329.206 175.101,329.206 cw(c175.101,329.106) 175.201,329.106 175.201,328.807 cw(c175.101,328.807) 175.101,328.707 174.69,328.707 173.3,328.707 ccw(c173.3,328.607) 173.2,328.607 173.2,328.308 ccw(c173.3,328.308) 173.3,328.208 174.69,328.208 175.362,328.208 cw(c175.362,328.109) 175.462,328.109 175.462,327.809 cw(c175.362,327.809) 175.362,327.71 174.69,327.71 173.297,327.71 ccw(c173.297,327.61) 173.198,327.61 173.198,327.311 ccw(c173.297,327.311) 173.297,327.211 174.618,327.211 cw(c174.618,327.139) 174.69,327.139 174.69,326.904 174.796,326.798 cw(c174.725,326.728) 174.796,326.657 174.613,326.475 ccw(c174.684,326.405) 174.613,326.334 174.825,326.123 ccw(c174.896,326.193) 174.966,326.123 175.219,326.375 175.472,326.628 cw(c175.542,326.558) 175.613,326.628 175.824,326.417 cw(c175.754,326.346) 175.824,326.276 175.571,326.023 175.319,325.77 ccw(c175.389,325.699) 175.319,325.629 175.53,325.417 ccw(c175.601,325.488) 175.671,325.417 175.924,325.67 176.177,325.923 cw(c176.247,325.852) 176.318,325.923 176.529,325.711 cw(c176.459,325.641) 176.529,325.57 176.276,325.318 176.024,325.065 ccw(c176.094,324.994) 176.024,324.924 176.235,324.712 ccw(c176.306,324.783) 176.376,324.712 176.629,324.965 176.882,325.218 cw(c176.952,325.147) 177.023,325.218 177.234,325.006 cw(c177.164,324.936) 177.234,324.865 177.052,324.683 ccw(c177.123,324.613) 177.052,324.542 177.283,324.311 177.292,324.302 177.292,319.214 177.292,318.541 ccw(c177.392,318.541) 177.392,318.442 177.445,318.442 cw(c177.445,318.342) 177.545,318.342 177.545,318.043 cw(c177.445,318.043) 177.445,317.943 177.292,317.943 177.099,317.943 ccw(c177.099,317.843) 176.999,317.843 176.999,317.544 ccw(c177.099,317.544) 177.099,317.444 177.192,317.444 cw(c177.192,317.345) 177.292,317.345 177.292,317.195 177,316.903 177,316.132 177.978,315.154 177.978,312.933 v1(178.884,312.027)
DDR4_DQ33: U1.V23 U9.F4 | length 40.2
  L1 w0.116: U9.F4@167.676,332.06 v4(168.079,331.657) ; v1(178.909,311.027) U1.V23@179.397,310.539
  L12 (Sign) w0.092: v4(168.079,331.657) 168.415,331.657 cw(c168.415,331.568) 168.504,331.568 168.504,329.324 ccw(c168.618,329.324) 168.618,329.209 168.732,329.209 ccw(c168.732,329.349) 168.872,329.349 168.872,330.848 cw(c168.974,330.848) 168.974,330.949 169.086,330.949 cw(c169.086,330.848) 169.188,330.848 169.188,328.792 ccw(c169.304,328.792) 169.304,328.676 169.398,328.676 cw(c169.398,328.542) 169.532,328.542 169.532,327.79 ccw(c169.675,327.79) 169.675,327.647 169.783,327.647 ccw(c169.783,327.762) 169.897,327.762 169.897,330.26 cw(c170.028,330.26) 170.028,330.39 170.713,330.39 171.032,330.072 171.249,330.072 171.986,329.334 171.986,326.539 172.05,326.476 cw(c171.955,326.381) 172.05,326.286 172.026,326.262 ccw(c172.121,326.167) 172.026,326.072 172.152,325.945 ccw(c172.247,326.04) 172.342,325.945 172.461,326.064 172.472,326.075 cw(c172.567,325.98) 172.662,326.075 172.789,325.948 cw(c172.694,325.853) 172.789,325.758 172.778,325.748 172.653,325.623 ccw(c172.748,325.528) 172.653,325.433 172.78,325.306 ccw(c172.875,325.401) 172.97,325.306 173.095,325.431 173.105,325.442 cw(c173.2,325.347) 173.295,325.442 173.422,325.315 cw(c173.327,325.22) 173.422,325.125 173.411,325.115 173.287,324.99 ccw(c173.382,324.895) 173.287,324.8 173.413,324.673 ccw(c173.508,324.768) 173.603,324.673 173.728,324.798 173.738,324.808 cw(c173.833,324.713) 173.928,324.808 174.055,324.682 cw(c173.96,324.587) 174.055,324.492 174.045,324.481 173.92,324.356 ccw(c174.015,324.261) 173.92,324.167 174.046,324.04 ccw(c174.141,324.135) 174.236,324.04 174.361,324.165 174.372,324.175 cw(c174.467,324.08) 174.562,324.175 174.688,324.049 cw(c174.593,323.954) 174.688,323.859 174.678,323.848 174.553,323.723 ccw(c174.648,323.628) 174.553,323.533 174.68,323.407 ccw(c174.775,323.502) 174.87,323.407 174.9,323.436 cw(c174.994,323.341) 175.089,323.436 175.244,323.281 175.244,322.923 175.778,322.389 175.778,322.233 ccw(c175.845,322.233) 175.845,322.166 cw(c175.845,322.054) 175.957,322.054 175.957,321.83 cw(c175.845,321.83) 175.845,321.718 175.778,321.718 175.711,321.718 ccw(c175.711,321.606) 175.599,321.606 175.599,321.382 ccw(c175.711,321.382) 175.711,321.27 ; 175.691,321.27 cw(c175.691,321.183) 175.778,321.183 175.778,317.947 176.211,317.514 176.211,316.273 176.251,316.233 176.251,316.067 177.402,314.915 177.402,312.612 177.664,312.35 177.664,312.272 178.104,311.832 178.104,311.704 178.561,311.247 178.581,311.247 178.801,311.027 v1(178.909,311.027)
DDR4_DQ34: U1.U25 U9.H3 | length 40.7
  L1 w0.116: v4(170.472,333.257) U9.H3@170.876,333.66 ; U1.U25@178.397,312.539 v1(178.884,313.027)
  L12 (Sign) w0.092: v4(170.472,333.257) 171.363,333.257 175.654,328.966 175.654,327.147 176.623,326.178 177.528,325.272 177.81,324.99 cw(c177.74,324.92) 177.81,324.849 177.632,324.671 ccw(c177.703,324.601) 177.632,324.53 177.844,324.319 ccw(c177.914,324.389) 177.985,324.319 178.163,324.497 cw(c178.233,324.426) 178.304,324.497 178.41,324.391 178.41,324.155 178.41,323.819 cw(c178.31,323.819) 178.31,323.719 177.9,323.719 ccw(c177.9,323.619) 177.8,323.619 177.8,323.32 ccw(c177.9,323.32) 177.9,323.221 178.41,323.221 178.919,323.221 cw(c178.919,323.121) 179.019,323.121 179.019,322.822 cw(c178.919,322.822) 178.919,322.722 178.41,322.722 177.9,322.722 ccw(c177.9,322.622) 177.8,322.622 177.8,322.323 ccw(c177.9,322.323) 177.9,322.223 178.41,322.223 178.671,322.223 cw(c178.671,322.124) 178.771,322.124 178.771,321.825 cw(c178.671,321.825) 178.671,321.725 178.41,321.725 177.9,321.725 ccw(c177.9,321.625) 177.8,321.625 177.8,321.326 ccw(c177.9,321.326) 177.9,321.226 178.41,321.226 178.671,321.226 cw(c178.671,321.126) 178.771,321.126 178.771,320.827 cw(c178.671,320.827) 178.671,320.728 178.41,320.728 177.9,320.728 ccw(c177.9,320.628) 177.8,320.628 177.8,320.329 ccw(c177.9,320.329) 177.9,320.229 178.41,320.229 178.671,320.229 cw(c178.671,320.129) 178.771,320.129 178.771,319.83 cw(c178.671,319.83) 178.671,319.73 178.41,319.73 177.9,319.73 ccw(c177.9,319.631) 177.8,319.631 177.8,319.332 ccw(c177.9,319.332) 177.9,319.232 178.41,319.232 178.671,319.232 cw(c178.671,319.132) 178.771,319.132 178.771,318.833 cw(c178.671,318.833) 178.671,318.733 178.41,318.733 177.9,318.733 ccw(c177.9,318.633) 177.8,318.633 177.8,318.334 ccw(c177.9,318.334) 177.9,318.235 178.41,318.235 178.671,318.235 cw(c178.671,318.135) 178.771,318.135 178.771,317.836 cw(c178.671,317.836) 178.671,317.736 178.41,317.736 178.089,317.736 ccw(c178.089,317.636) 177.989,317.636 177.989,317.337 ccw(c178.089,317.337) 178.089,317.237 178.41,317.237 178.551,317.237 cw(c178.551,317.138) 178.651,317.138 178.651,316.839 cw(c178.551,316.839) 178.551,316.739 178.41,316.739 177.9,316.739 ccw(c177.9,316.639) 177.8,316.639 177.8,316.34 ccw(c177.9,316.34) 177.9,316.24 178.41,316.24 178.671,316.24 cw(c178.671,316.14) 178.771,316.14 178.771,315.841 cw(c178.671,315.841) 178.671,315.742 178.41,315.742 178.2,315.742 ccw(c178.2,315.642) 178.1,315.642 178.1,315.343 ccw(c178.2,315.343) 178.2,315.243 178.31,315.243 cw(c178.31,315.143) 178.41,315.143 178.41,314.994 178.884,314.519 v1(178.884,313.027)
DDR4_DQ35: U1.V24 U9.H4 | length 39.9
  L1 w0.116: U9.H4@167.676,333.66 v4(168.079,333.257) ; U1.V24@179.397,311.539 v1(179.884,311.052)
  L12 (Sign) w0.092: v4(168.079,333.257) 168.079,332.72 168.143,332.657 ccw(c168.238,332.751) 168.333,332.657 169.354,333.678 cw(c169.449,333.583) 169.544,333.678 169.671,333.551 cw(c169.576,333.456) 169.671,333.361 168.554,332.245 168.519,332.21 ccw(c168.614,332.115) 168.519,332.02 168.646,331.893 ccw(c168.741,331.988) 168.836,331.893 168.871,331.928 169.829,332.887 cw(c169.924,332.792) 170.019,332.887 170.146,332.76 cw(c170.051,332.665) 170.146,332.57 169.188,331.612 169.165,331.589 ccw(c169.26,331.494) 169.165,331.399 169.291,331.272 ccw(c169.386,331.367) 169.481,331.272 169.504,331.295 169.819,331.61 cw(c169.914,331.515) 170.009,331.61 170.136,331.483 cw(c170.041,331.388) 170.136,331.293 169.916,331.073 ccw(c170.011,330.978) 169.916,330.883 169.989,330.81 170.217,330.582 170.793,330.582 171.112,330.263 171.328,330.263 172.178,329.413 172.178,326.83 175.565,323.444 175.611,323.398 cw(c175.547,323.334) 175.611,323.271 175.486,323.146 ccw(c175.549,323.083) 175.486,323.02 175.676,322.83 ccw(c175.739,322.893) 175.803,322.83 175.927,322.954 cw(c175.991,322.891) 176.054,322.954 176.149,322.859 176.149,322.725 ccw(c176.239,322.725) 176.239,322.636 176.415,322.636 cw(c176.415,322.546) 176.505,322.546 176.505,322.277 cw(c176.415,322.277) 176.415,322.188 176.239,322.188 ccw(c176.239,322.098) 176.149,322.098 176.149,322.047 176.149,317.848 176.403,317.594 176.403,316.352 176.451,316.304 176.451,316.138 177.594,314.995 177.594,312.715 178.296,312.013 178.296,311.783 178.65,311.429 179.197,311.429 cw(c179.197,311.233) 179.393,311.233 179.393,310.801 ccw(c179.743,310.801) 179.743,310.452 180.111,310.452 ccw(c180.111,310.718) 180.378,310.718 ccw(c180.044,310.718) 180.044,311.052 v1(179.884,311.052)
DDR4_DQ36: U1.Y25 U9.H2 | length 38.8
  L1 w0.116: U9.H2@171.676,333.66 v4(172.079,333.257) ; v1(180.909,313.027) U1.Y25@181.397,312.539
  L12 (Sign) w0.092: v4(172.079,333.257) 172.079,332.822 175.91,328.992 175.91,327.163 178.602,324.47 178.602,324.445 179.553,323.494 179.553,322.847 179.553,322.514 cw(c179.453,322.514) 179.453,322.414 179.063,322.414 ccw(c179.063,322.315) 178.963,322.315 178.963,322.016 ccw(c179.063,322.016) 179.063,321.916 179.553,321.916 180.042,321.916 cw(c180.042,321.816) 180.142,321.816 180.142,321.517 cw(c180.042,321.517) 180.042,321.417 179.553,321.417 179.063,321.417 ccw(c179.063,321.318) 178.963,321.318 178.963,321.018 ccw(c179.063,321.018) 179.063,320.919 179.553,320.919 180.042,320.919 cw(c180.042,320.819) 180.142,320.819 180.142,320.52 cw(c180.042,320.52) 180.042,320.42 179.553,320.42 179.063,320.42 ccw(c179.063,320.32) 178.963,320.32 178.963,320.021 ccw(c179.063,320.021) 179.063,319.921 179.553,319.921 180.042,319.921 cw(c180.042,319.822) 180.142,319.822 180.142,319.523 cw(c180.042,319.523) 180.042,319.423 179.553,319.423 179.063,319.423 ccw(c179.063,319.323) 178.963,319.323 178.963,319.024 ccw(c179.063,319.024) 179.063,318.924 179.553,318.924 180.042,318.924 cw(c180.042,318.825) 180.142,318.825 180.142,318.525 cw(c180.042,318.525) 180.042,318.426 179.553,318.426 179.063,318.426 ccw(c179.063,318.326) 178.963,318.326 178.963,318.027 ccw(c179.063,318.027) 179.063,317.927 179.553,317.927 180.042,317.927 cw(c180.042,317.827) 180.142,317.827 180.142,317.528 cw(c180.042,317.528) 180.042,317.428 179.553,317.428 179.288,317.428 ccw(c179.288,317.329) 179.188,317.329 179.188,317.03 ccw(c179.288,317.03) 179.288,316.93 179.553,316.93 180.042,316.93 cw(c180.042,316.83) 180.142,316.83 180.142,316.531 cw(c180.042,316.531) 180.042,316.431 179.553,316.431 179.063,316.431 ccw(c179.063,316.332) 178.963,316.332 178.963,316.032 ccw(c179.063,316.032) 179.063,315.933 179.453,315.933 cw(c179.453,315.833) 179.553,315.833 179.553,315.683 180.909,314.326 v1(180.909,313.027)
DDR4_DQ37: U1.AA23 U9.H5 | length 37.4
  L1 w0.116: v4(166.472,333.257) U9.H5@166.876,333.66 ; v1(181.909,310.052) U1.AA23@182.397,310.539
  L12 (Sign) w0.092: v4@166.472,333.257 166.472,333.934 166.998,334.46 171.343,334.46 171.78,334.023 172.683,334.023 176.451,330.255 176.451,327.244 181.47,322.224 181.47,315.824 181.985,315.309 181.985,312.941 181.508,312.464 181.508,311.839 181.781,311.566 182.172,311.566 182.397,311.341 182.397,310.539 v1(181.909,310.052)
DDR4_DQ38: U1.AA25 U9.J3 | length 38.2
  L1 w0.116: U9.J3@170.876,334.46 v4(171.279,334.864) ; v1(181.909,312.052) U1.AA25@182.397,312.539
  L12 (Sign) w0.092: v4(171.279,334.864) 171.929,334.215 172.872,334.215 173.022,334.215 ccw(c173.022,334.314) 173.122,334.314 173.122,334.619 cw(c173.221,334.619) 173.221,334.719 173.521,334.719 cw(c173.521,334.619) 173.62,334.619 173.62,334.215 173.62,333.705 ccw(c173.72,333.705) 173.72,333.605 174.019,333.605 ccw(c174.019,333.705) 174.119,333.705 174.119,334.215 174.119,334.725 cw(c174.219,334.725) 174.219,334.824 174.518,334.824 cw(c174.518,334.725) 174.617,334.725 174.617,334.215 174.617,333.705 ccw(c174.717,333.705) 174.717,333.605 175.016,333.605 ccw(c175.016,333.705) 175.116,333.705 175.116,334.215 175.116,334.725 cw(c175.216,334.725) 175.216,334.824 175.515,334.824 cw(c175.515,334.725) 175.615,334.725 175.615,334.314 ccw(c175.714,334.314) 175.714,334.215 175.844,334.215 176.122,334.215 176.643,333.694 176.643,333.544 ccw(c176.743,333.544) 176.743,333.445 176.98,333.445 cw(c176.98,333.345) 177.08,333.345 177.08,333.046 cw(c176.98,333.046) 176.98,332.946 176.643,332.946 176.306,332.946 ccw(c176.306,332.846) 176.206,332.846 176.206,332.547 ccw(c176.306,332.547) 176.306,332.448 176.543,332.448 cw(c176.543,332.348) 176.643,332.348 176.643,331.483 176.643,327.352 179.36,324.634 179.36,324.617 182.372,321.605 182.372,315.584 182.177,315.389 182.177,312.319 v1(181.909,312.052)
DDR4_DQ39: U1.Y23 U9.J4 | length 39.7
  L1 w0.116: v4(167.272,334.057) U9.J4@167.676,334.46 ; U1.Y23@181.397,310.539 v1(181.884,311.027)
  L12 (Sign) w0.092: 170.679,334.057 171.12,333.616 172.273,333.616 172.466,333.424 172.466,333.054 176.102,329.418 176.102,327.262 180.81,322.554 180.81,321.462 180.81,320.825 cw(c180.71,320.825) 180.71,320.725 180.513,320.725 ccw(c180.513,320.626) 180.414,320.626 180.414,320.327 ccw(c180.513,320.327) 180.513,320.227 180.81,320.227 181.106,320.227 cw(c181.106,320.127) 181.206,320.127 181.206,319.828 cw(c181.106,319.828) 181.106,319.728 180.81,319.728 180.513,319.728 ccw(c180.513,319.628) 180.414,319.628 180.414,319.329 ccw(c180.513,319.329) 180.513,319.23 180.81,319.23 181.106,319.23 cw(c181.106,319.13) 181.206,319.13 181.206,318.831 cw(c181.106,318.831) 181.106,318.731 180.81,318.731 180.513,318.731 ccw(c180.513,318.631) 180.414,318.631 180.414,318.332 ccw(c180.513,318.332) 180.513,318.232 180.81,318.232 181.106,318.232 cw(c181.106,318.133) 181.206,318.133 181.206,317.834 cw(c181.106,317.834) 181.106,317.734 180.81,317.734 180.513,317.734 ccw(c180.513,317.634) 180.414,317.634 180.414,317.335 ccw(c180.513,317.335) 180.513,317.235 180.81,317.235 181.106,317.235 cw(c181.106,317.135) 181.206,317.135 181.206,316.836 cw(c181.106,316.836) 181.106,316.737 180.81,316.737 180.513,316.737 ccw(c180.513,316.637) 180.414,316.637 180.414,316.338 ccw(c180.513,316.338) 180.513,316.238 180.71,316.238 cw(c180.71,316.138) 180.81,316.138 180.81,315.989 181.793,315.006 181.793,313.375 181.316,312.899 181.316,311.595 v1(181.884,311.027)
  L12 (Sign) w0.1: v4(167.272,334.057) 170.679,334.057
DDR4_DQ40: U1.P23 U9.A3 | length 31.5
  L1 w0.116: v4(170.472,327.657) U9.A3@170.876,328.06 ; U1.P23@175.397,310.539 v1(175.884,311.027)
  L12 (Sign) w0.092: v4(170.472,327.657) 170.472,325.12 170.472,325.056 170.472,324.682 cw(c170.348,324.682) 170.348,324.558 169.524,324.558 ccw(c169.524,324.433) 169.399,324.433 169.399,324.184 ccw(c169.524,324.184) 169.524,324.059 170.348,324.059 cw(c170.348,323.934) 170.472,323.934 170.472,323.685 cw(c170.348,323.685) 170.348,323.56 170.226,323.56 ccw(c170.226,323.436) 170.101,323.436 170.101,323.186 ccw(c170.226,323.186) 170.226,323.062 170.348,323.062 cw(c170.348,322.937) 170.472,322.937 170.472,322.813 170.574,322.711 171.287,321.998 cw(c171.199,321.91) 171.287,321.821 171.245,321.779 ccw(c171.333,321.691) 171.245,321.603 171.421,321.427 ccw(c171.509,321.515) 171.597,321.427 171.728,321.557 cw(c171.788,321.497) 171.847,321.557 172.08,321.324 cw(c172.02,321.264) 172.08,321.204 171.95,321.074 ccw(c172.038,320.986) 171.95,320.898 172.126,320.722 ccw(c172.214,320.81) 172.303,320.722 172.433,320.852 cw(c172.48,320.805) 172.527,320.852 172.785,320.594 cw(c172.738,320.546) 172.785,320.499 172.655,320.369 ccw(c172.743,320.281) 172.655,320.193 172.831,320.016 ccw(c172.92,320.105) 173.008,320.016 173.138,320.147 cw(c173.185,320.1) 173.232,320.147 173.491,319.889 cw(c173.443,319.841) 173.491,319.794 173.36,319.664 ccw(c173.448,319.576) 173.36,319.488 173.537,319.311 ccw(c173.625,319.399) 173.713,319.311 173.755,319.353 cw(c173.843,319.265) 173.931,319.353 174.019,319.265 174.079,319.206 174.079,319.081 ccw(c174.204,319.081) 174.204,318.956 174.401,318.956 cw(c174.401,318.832) 174.526,318.832 174.526,318.583 cw(c174.401,318.583) 174.401,318.458 174.204,318.458 ccw(c174.204,318.333) 174.079,318.333 174.079,318.072 174.079,317.675 174.076,317.672 174.076,317.406 174.079,317.403 174.079,316.675 174.076,316.672 174.076,316.406 174.079,316.403 174.079,315.675 174.076,315.672 174.076,315.406 174.079,315.403 174.079,315.303 174.23,315.152 174.484,315.152 175.362,314.274 175.362,313.919 175.158,313.716 175.158,312.338 175.305,312.191 175.305,311.875 175.524,311.656 176.073,311.656 176.076,311.658 176.234,311.658 176.488,311.912 176.488,312.191 176.72,312.423 177.048,312.423 177.28,312.191 177.28,312.113 177.718,311.675 177.718,311.406 177.508,311.196 177.032,311.196 ccw(c177.032,311.114) 176.949,311.114 176.949,310.483 cw(c176.771,310.483) 176.771,310.306 176.371,310.306 cw(c176.371,310.452) 176.225,310.452 176.225,310.686 ccw(c175.884,310.686) v1(175.884,311.027)
DDR4_DQ41: U1.R23 U9.B5 | length 33.5
  L1 w0.116: v4(166.472,328.457) U9.B5@166.876,328.86 ; v1(175.909,310.052) U1.R23@176.397,310.539
  L1 w0.25: v4(166.472,327.657) 166.876,328.06
  L12 (Sign) w0.092: v4(166.472,328.457) 166.917,328.012 166.917,322.743 167.036,322.624 167.062,322.599 cw(c166.973,322.511) 167.062,322.422 166.917,322.278 ccw(c167.005,322.19) 166.917,322.102 167.094,321.926 ccw(c167.182,322.014) 167.27,321.926 167.502,322.158 167.706,322.362 cw(c167.795,322.274) 167.883,322.362 168.059,322.186 cw(c167.971,322.098) 168.059,322.01 167.855,321.805 167.622,321.573 ccw(c167.711,321.485) 167.622,321.397 167.799,321.221 ccw(c167.887,321.309) 167.975,321.221 168.207,321.453 168.41,321.656 cw(c168.499,321.568) 168.587,321.656 168.763,321.48 cw(c168.675,321.392) 168.763,321.303 168.56,321.1 168.328,320.868 ccw(c168.416,320.78) 168.328,320.692 168.504,320.515 ccw(c168.592,320.604) 168.68,320.515 168.912,320.748 169.062,320.897 cw(c169.15,320.809) 169.238,320.897 169.414,320.721 cw(c169.326,320.632) 169.414,320.544 169.265,320.395 169.033,320.163 ccw(c169.121,320.075) 169.033,319.987 169.209,319.81 ccw(c169.297,319.898) 169.385,319.81 169.618,320.043 169.767,320.192 cw(c169.855,320.104) 169.943,320.192 170.119,320.015 cw(c170.031,319.927) 170.119,319.839 169.97,319.69 169.738,319.458 ccw(c169.826,319.37) 169.738,319.281 169.914,319.105 ccw(c170.002,319.193) 170.09,319.105 170.235,319.249 cw(c170.323,319.161) 170.411,319.249 170.499,319.161 170.499,319.037 ccw(c170.624,319.037) 170.624,318.912 170.813,318.912 cw(c170.813,318.787) 170.937,318.787 170.937,318.538 cw(c170.813,318.538) 170.813,318.413 170.624,318.413 ccw(c170.624,318.289) 170.499,318.289 170.499,318.039 ccw(c170.624,318.039) 170.624,317.915 170.813,317.915 cw(c170.813,317.79) 170.937,317.79 170.937,317.541 cw(c170.813,317.541) 170.813,317.416 170.624,317.416 ccw(c170.624,317.292) 170.499,317.292 170.499,317.042 ccw(c170.624,317.042) 170.624,316.918 170.813,316.918 cw(c170.813,316.793) 170.937,316.793 170.937,316.544 cw(c170.813,316.544) 170.813,316.419 170.624,316.419 ccw(c170.624,316.294) 170.499,316.294 170.499,316.167 170.912,315.754 170.912,313.477 171.233,313.157 171.601,313.157 173.828,310.93 174.719,310.93 175.597,310.052 v1(175.909,310.052)
DDR4_DQ42: U1.T23 U9.C3 | length 30.8
  L1 w0.116: v4(170.472,329.257) U9.C3@170.876,329.66 ; U1.T23@177.397,310.539 v2(177.884,310.052)
  L12 (Sign) w0.092: v4(170.472,329.257) 170.472,328.975 170.793,328.654 170.793,327.465 170.709,327.381 170.709,323.429 170.788,323.35 ccw(c170.868,323.429) 170.947,323.35 171.032,323.436 cw(c171.112,323.357) 171.191,323.436 171.349,323.278 cw(c171.27,323.198) 171.349,323.119 171.184,322.954 171.019,322.79 ccw(c171.098,322.71) 171.019,322.631 171.178,322.473 ccw(c171.257,322.552) 171.336,322.473 171.501,322.638 171.666,322.803 cw(c171.745,322.723) 171.824,322.803 171.982,322.644 cw(c171.903,322.565) 171.982,322.486 171.817,322.321 171.653,322.156 ccw(c171.732,322.077) 171.653,321.998 171.811,321.84 ccw(c171.89,321.919) 171.969,321.84 172.134,322.004 172.299,322.169 cw(c172.378,322.09) 172.457,322.169 172.616,322.011 cw(c172.536,321.932) 172.616,321.853 172.451,321.688 172.286,321.523 ccw(c172.365,321.444) 172.286,321.365 172.444,321.206 ccw(c172.523,321.286) 172.603,321.206 172.767,321.371 172.932,321.536 cw(c173.011,321.457) 173.091,321.536 173.249,321.378 cw(c173.17,321.299) 173.249,321.219 173.084,321.055 172.919,320.89 ccw(c172.998,320.811) 172.919,320.731 173.077,320.573 ccw(c173.157,320.652) 173.236,320.573 173.401,320.738 173.541,320.878 cw(c173.62,320.799) 173.699,320.878 173.858,320.72 cw(c173.779,320.641) 173.858,320.562 173.717,320.421 173.552,320.256 ccw(c173.632,320.177) 173.552,320.098 173.711,319.94 ccw(c173.79,320.019) 173.869,319.94 173.955,320.025 cw(c174.034,319.946) 174.113,320.025 174.387,319.751 174.718,319.421 174.718,315.218 175.552,314.384 175.552,314.355 175.554,314.354 175.554,313.839 175.552,313.838 175.552,313.779 175.362,313.588 175.362,312.885 175.616,312.631 177.112,312.631 177.472,312.27 177.472,312.192 177.91,311.755 177.91,311.627 178.371,311.165 178.371,310.539 v2(177.884,310.052)
DDR4_DQ43: U1.P26 U9.C4 | length 29.3
  L1 w0.116: U9.C4@167.676,329.66 v4(168.079,329.257) ; v1(174.909,314.027) U1.P26@175.397,313.539
  L12 (Sign) w0.092: v4(168.079,329.257) 169.1,328.236 169.1,328.111 cw(c168.976,328.111) 168.976,327.986 168.612,327.986 ccw(c168.612,327.862) 168.487,327.862 168.487,327.612 ccw(c168.612,327.612) 168.612,327.488 169.1,327.488 169.418,327.488 cw(c169.418,327.363) 169.543,327.363 169.543,327.114 cw(c169.418,327.114) 169.418,326.989 169.1,326.989 168.188,326.989 ccw(c168.188,326.864) 168.064,326.864 168.064,326.615 ccw(c168.188,326.615) 168.188,326.491 169.1,326.491 170.013,326.491 cw(c170.013,326.366) 170.137,326.366 170.137,326.117 cw(c170.013,326.117) 170.013,325.992 169.1,325.992 168.188,325.992 ccw(c168.188,325.867) 168.064,325.867 168.064,325.618 ccw(c168.188,325.618) 168.188,325.493 169.1,325.493 170.013,325.493 cw(c170.013,325.369) 170.137,325.369 170.137,325.119 cw(c170.013,325.119) 170.013,324.995 169.204,324.995 ccw(c169.204,324.891) 169.1,324.891 169.1,323.418 173.838,318.681 173.838,314.645 174.456,314.027 v1(174.909,314.027)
